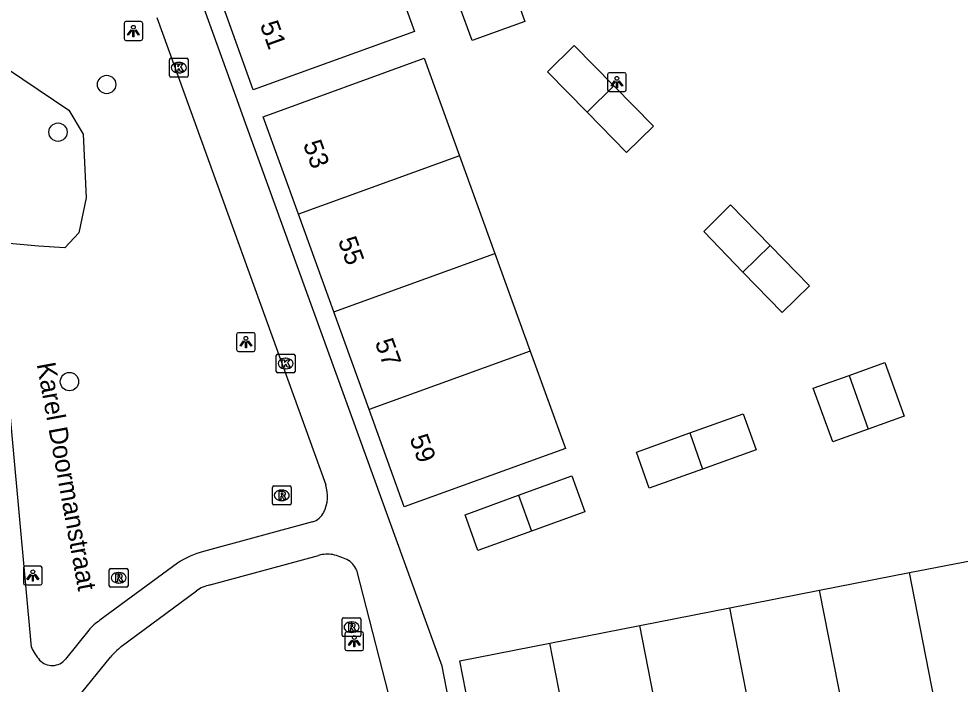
# Model space of a CAD drawing. Extents: x 160379 to 161131, y 383940 to 384849.
# Drawn here: x 160658.5 to 160708.7, y 384516.2 to 384551.6 of the extents above; entities that cross this region are included whole.
import ezdxf

# ---------------------------------------------------------------- set-up
doc = ezdxf.new("R2010")
doc.units = 0
for name, color, linetype in [('IMGEO_Boom', 7, 'Continuous'), ('IMGEO_Groenvoorziening', 7, 'Continuous'), ('IMGEO_Kolk', 7, 'Continuous'), ('IMGEO_Lichtpunt', 7, 'Continuous'), ('IMGEO_Openbare_ruimte_label', 7, 'Continuous'), ('IMGEO_Pand', 7, 'Continuous'), ('IMGEO_Pand_nummerreeks', 7, 'Continuous'), ('IMGEO_Rioolput', 7, 'Continuous'), ('IMGEO_Voetgangersgebied_open', 7, 'Continuous')]:
    doc.layers.add(name, color=color, linetype=linetype)

msp = doc.modelspace()

# ---------------------------------------------------------------- linework, layer by layer
at = {"layer": 'IMGEO_Boom'}
for centre in [(160663.171, 384548.138), (160660.578, 384545.599), (160661.19, 384532.308)]:
    msp.add_circle(centre, 0.489, dxfattribs=at)
at = {"layer": 'IMGEO_Groenvoorziening'}
msp.add_lwpolyline([(160656.229, 384550.075), (160661.151, 384546.774), (160661.917, 384545.486), (160662.071, 384542.104), (160661.684, 384540.236), (160660.94, 384539.438), (160659.532, 384539.533), (160657.181, 384539.738)], dxfattribs=at)
at = {"layer": 'IMGEO_Kolk'}
for p, q in [((160666.521, 384548.609), (160666.521, 384549.461)), ((160666.596, 384549.535), (160667.448, 384549.535)), ((160667.522, 384549.461), (160667.522, 384548.609)), ((160667.009, 384549.315), (160667.034, 384549.315)), ((160667.448, 384548.535), (160666.596, 384548.535)), ((160667.032, 384548.755), (160667.007, 384548.755)), ((160672.217, 384532.844), (160672.217, 384533.696)), ((160672.292, 384533.77), (160673.144, 384533.77)), ((160672.705, 384533.55), (160672.73, 384533.55)), ((160673.218, 384533.696), (160673.218, 384532.844)), ((160672.728, 384532.99), (160672.703, 384532.99)), ((160673.144, 384532.77), (160672.292, 384532.77))]:
    msp.add_line(p, q, dxfattribs=at)
for points in [[(160666.521, 384548.609), (160666.521, 384549.461)], [(160666.596, 384549.535), (160667.448, 384549.535)], [(160667.522, 384549.461), (160667.522, 384548.609)], [(160666.842, 384549.235), (160666.965, 384549.235), (160666.965, 384549.084), (160667.095, 384549.235), (160667.259, 384549.235), (160667.113, 384549.084), (160667.266, 384548.835), (160667.114, 384548.835), (160667.029, 384548.999), (160666.965, 384548.932), (160666.965, 384548.835), (160666.842, 384548.835), (160666.842, 384549.235)], [(160667.448, 384548.535), (160666.596, 384548.535)], [(160672.217, 384532.844), (160672.217, 384533.696)], [(160672.292, 384533.77), (160673.144, 384533.77)], [(160672.538, 384533.47), (160672.661, 384533.47), (160672.661, 384533.319), (160672.791, 384533.47), (160672.955, 384533.47), (160672.809, 384533.319), (160672.962, 384533.07), (160672.81, 384533.07), (160672.725, 384533.234), (160672.661, 384533.167), (160672.661, 384533.07), (160672.538, 384533.07), (160672.538, 384533.47)], [(160673.218, 384533.696), (160673.218, 384532.844)], [(160673.144, 384532.77), (160672.292, 384532.77)]]:
    msp.add_lwpolyline(points, dxfattribs=at)
for centre, start, end in [((160666.598, 384549.459), 91.552, 178.448), ((160666.598, 384549.459), 91.552, 178.448), ((160667.446, 384549.459), 1.552, 88.448), ((160667.446, 384549.459), 1.552, 88.448), ((160666.598, 384548.611), 181.552, 268.448), ((160666.598, 384548.611), 181.552, 268.448), ((160667.446, 384548.611), 271.552, 358.448), ((160667.446, 384548.611), 271.552, 358.448), ((160672.294, 384533.694), 91.552, 178.448), ((160672.294, 384533.694), 91.552, 178.448), ((160673.142, 384533.694), 1.552, 88.448), ((160673.142, 384533.694), 1.552, 88.448), ((160672.294, 384532.846), 181.552, 268.448), ((160672.294, 384532.846), 181.552, 268.448), ((160673.142, 384532.846), 271.552, 358.448), ((160673.142, 384532.846), 271.552, 358.448)]:
    msp.add_arc(centre, 0.0765, start, end, dxfattribs=at)
for centre, major_axis, ratio, start_param, end_param in [((160667.008, 384549.035), (-0.387, 0.002), 0.722429, 4.712389, 7.853982), ((160667.033, 384549.035), (-0.39, 0.002), 0.717154, 1.570796, 4.712389), ((160672.704, 384533.27), (-0.387, 0.002), 0.722429, 4.712389, 7.853982), ((160672.729, 384533.27), (-0.39, 0.002), 0.717154, 1.570796, 4.712389)]:
    msp.add_ellipse(centre, major_axis=major_axis, ratio=ratio, start_param=start_param, end_param=end_param, dxfattribs=at)
at = {"layer": 'IMGEO_Lichtpunt'}
for p, q in [((160665, 384551.487), (160664.192, 384551.487)), ((160665, 384551.487), (160664.192, 384551.487)), ((160664.098, 384551.392), (160664.098, 384550.585)), ((160664.098, 384551.392), (160664.098, 384550.585)), ((160665.094, 384550.585), (160665.094, 384551.392)), ((160665.094, 384550.585), (160665.094, 384551.392)), ((160664.192, 384550.491), (160665, 384550.491)), ((160664.192, 384550.491), (160665, 384550.491)), ((160689.886, 384548.669), (160689.886, 384547.862)), ((160689.886, 384548.669), (160689.886, 384547.862)), ((160690.788, 384548.764), (160689.98, 384548.764)), ((160690.788, 384548.764), (160689.98, 384548.764)), ((160690.882, 384547.862), (160690.882, 384548.669)), ((160690.882, 384547.862), (160690.882, 384548.669)), ((160689.98, 384547.768), (160690.788, 384547.768)), ((160689.98, 384547.768), (160690.788, 384547.768)), ((160671.003, 384534.913), (160670.195, 384534.913)), ((160671.003, 384534.913), (160670.195, 384534.913)), ((160670.101, 384534.818), (160670.101, 384534.011)), ((160670.101, 384534.818), (160670.101, 384534.011)), ((160671.097, 384534.011), (160671.097, 384534.818)), ((160671.097, 384534.011), (160671.097, 384534.818)), ((160670.195, 384533.917), (160671.003, 384533.917)), ((160670.195, 384533.917), (160671.003, 384533.917)), ((160658.736, 384522.38), (160658.736, 384521.573)), ((160658.736, 384522.38), (160658.736, 384521.573)), ((160659.638, 384522.475), (160658.83, 384522.475)), ((160659.638, 384522.475), (160658.83, 384522.475)), ((160659.732, 384521.573), (160659.732, 384522.38)), ((160659.732, 384521.573), (160659.732, 384522.38)), ((160658.83, 384521.479), (160659.638, 384521.479)), ((160658.83, 384521.479), (160659.638, 384521.479)), ((160675.881, 384518.876), (160675.881, 384518.069)), ((160675.881, 384518.876), (160675.881, 384518.069)), ((160676.783, 384518.971), (160675.975, 384518.971)), ((160676.783, 384518.971), (160675.975, 384518.971)), ((160676.877, 384518.069), (160676.877, 384518.876)), ((160676.877, 384518.069), (160676.877, 384518.876)), ((160675.975, 384517.975), (160676.783, 384517.975)), ((160675.975, 384517.975), (160676.783, 384517.975))]:
    msp.add_line(p, q, dxfattribs=at)
for points in [[(160664.472, 384551.056), (160664.511, 384551.028), (160664.323, 384550.766), (160664.285, 384550.793), (160664.472, 384551.056)], [(160664.574, 384551.008), (160664.621, 384551.008), (160664.621, 384550.686), (160664.574, 384550.686), (160664.574, 384551.008)], [(160664.684, 384551.028), (160664.722, 384551.055), (160664.909, 384550.793), (160664.87, 384550.765), (160664.684, 384551.028)], [(160690.26, 384548.333), (160690.299, 384548.305), (160690.111, 384548.043), (160690.073, 384548.07), (160690.26, 384548.333)], [(160690.362, 384548.285), (160690.409, 384548.285), (160690.409, 384547.963), (160690.362, 384547.963), (160690.362, 384548.285)], [(160690.472, 384548.305), (160690.51, 384548.332), (160690.697, 384548.07), (160690.658, 384548.042), (160690.472, 384548.305)], [(160670.475, 384534.482), (160670.514, 384534.454), (160670.326, 384534.192), (160670.288, 384534.219), (160670.475, 384534.482)], [(160670.577, 384534.434), (160670.624, 384534.434), (160670.624, 384534.112), (160670.577, 384534.112), (160670.577, 384534.434)], [(160670.687, 384534.454), (160670.725, 384534.481), (160670.912, 384534.219), (160670.873, 384534.191), (160670.687, 384534.454)], [(160659.11, 384522.044), (160659.149, 384522.016), (160658.961, 384521.754), (160658.923, 384521.781), (160659.11, 384522.044)], [(160659.212, 384521.996), (160659.259, 384521.996), (160659.259, 384521.674), (160659.212, 384521.674), (160659.212, 384521.996)], [(160659.322, 384522.016), (160659.36, 384522.043), (160659.547, 384521.781), (160659.508, 384521.753), (160659.322, 384522.016)], [(160676.255, 384518.54), (160676.294, 384518.512), (160676.106, 384518.25), (160676.068, 384518.277), (160676.255, 384518.54)], [(160676.357, 384518.492), (160676.404, 384518.492), (160676.404, 384518.17), (160676.357, 384518.17), (160676.357, 384518.492)], [(160676.467, 384518.512), (160676.505, 384518.539), (160676.692, 384518.277), (160676.653, 384518.249), (160676.467, 384518.512)]]:
    msp.add_lwpolyline(points, dxfattribs=at)
for centre in [(160664.597, 384551.19), (160690.385, 384548.467), (160670.6, 384534.616), (160659.235, 384522.178), (160676.38, 384518.674)]:
    msp.add_circle(centre, 0.0994, dxfattribs=at)
for centre, start, end in [((160664.192, 384551.392), 90, 180), ((160664.192, 384551.392), 90, 180), ((160665, 384551.392), 0, 90), ((160665, 384551.392), 0, 90), ((160664.192, 384550.585), 180, 270), ((160664.192, 384550.585), 180, 270), ((160665, 384550.585), 270, 0), ((160665, 384550.585), 270, 360), ((160689.98, 384548.669), 90, 180), ((160689.98, 384548.669), 90, 180), ((160690.788, 384548.669), 0, 90), ((160690.788, 384548.669), 0, 90), ((160689.98, 384547.862), 180, 270), ((160689.98, 384547.862), 180, 270), ((160690.788, 384547.862), 270, 0), ((160690.788, 384547.862), 270, 360), ((160670.195, 384534.818), 90, 180), ((160670.195, 384534.818), 90, 180), ((160671.003, 384534.818), 0, 90), ((160671.003, 384534.818), 0, 90), ((160670.195, 384534.011), 180, 270), ((160670.195, 384534.011), 180, 270), ((160671.003, 384534.011), 270, 0), ((160671.003, 384534.011), 270, 360), ((160658.83, 384522.38), 90, 180), ((160658.83, 384522.38), 90, 180), ((160659.638, 384522.38), 0, 90), ((160659.638, 384522.38), 0, 90), ((160658.83, 384521.573), 180, 270), ((160658.83, 384521.573), 180, 270), ((160659.638, 384521.573), 270, 0), ((160659.638, 384521.573), 270, 360), ((160675.975, 384518.876), 90, 180), ((160675.975, 384518.876), 90, 180), ((160676.783, 384518.876), 0, 90), ((160676.783, 384518.876), 0, 90), ((160675.975, 384518.069), 180, 270), ((160675.975, 384518.069), 180, 270), ((160676.783, 384518.069), 270, 0), ((160676.783, 384518.069), 270, 360)]:
    msp.add_arc(centre, 0.0946, start, end, dxfattribs=at)
at = {"layer": 'IMGEO_Pand'}
for points in [[(160677.9, 384555.621), (160679.591, 384550.956), (160670.993, 384547.855), (160669.308, 384552.507)], [(160685.481, 384551.498), (160682.659, 384550.476), (160681.973, 384552.374), (160684.794, 384553.395), (160685.481, 384551.498)], [(160688.789, 384546.663), (160686.675, 384548.816), (160688.102, 384550.217), (160690.216, 384548.064)], [(160673.396, 384541.222), (160671.511, 384546.422), (160680.104, 384549.537), (160681.989, 384544.337)], [(160690.216, 384548.064), (160692.33, 384545.911), (160690.903, 384544.51), (160688.789, 384546.663)], [(160688.789, 384546.663), (160690.216, 384548.064)], [(160681.989, 384544.337), (160673.396, 384541.222)], [(160681.989, 384544.337), (160683.874, 384539.137)], [(160697.105, 384538.147), (160695.015, 384540.299), (160696.434, 384541.723), (160698.558, 384539.558)], [(160675.28, 384536.022), (160673.396, 384541.222)], [(160698.558, 384539.558), (160700.659, 384537.417), (160699.195, 384535.995), (160697.105, 384538.147)], [(160697.105, 384538.147), (160698.558, 384539.558)], [(160675.28, 384536.022), (160683.874, 384539.137)], [(160683.874, 384539.137), (160685.758, 384533.937)], [(160677.165, 384530.822), (160675.28, 384536.022)], [(160685.758, 384533.937), (160687.643, 384528.737), (160679.045, 384525.635), (160677.165, 384530.822)], [(160685.758, 384533.937), (160677.165, 384530.822)], [(160702.767, 384532.64), (160704.679, 384533.323), (160705.699, 384530.47), (160703.788, 384529.782)], [(160703.788, 384529.782), (160701.895, 384529.1), (160700.854, 384531.956), (160702.767, 384532.64)], [(160702.767, 384532.64), (160703.788, 384529.782)], [(160694.269, 384529.57), (160697.117, 384530.589), (160697.802, 384528.674), (160694.956, 384527.649)], [(160694.956, 384527.649), (160692.111, 384526.624), (160691.421, 384528.551), (160694.269, 384529.57)], [(160694.269, 384529.57), (160694.956, 384527.649)], [(160685.13, 384526.254), (160687.977, 384527.293), (160688.674, 384525.363), (160685.821, 384524.336)], [(160685.821, 384524.336), (160682.968, 384523.309), (160682.287, 384525.217), (160685.13, 384526.254)], [(160685.13, 384526.254), (160685.821, 384524.336)], [(160705.987, 384522.128), (160710.782, 384523.068), (160711.912, 384517.267)], [(160701.193, 384521.188), (160705.987, 384522.128)], [(160707.752, 384513.125), (160705.987, 384522.128)], [(160696.398, 384520.249), (160701.193, 384521.188)], [(160702.957, 384512.188), (160701.193, 384521.188)], [(160691.603, 384519.309), (160696.398, 384520.249)], [(160698.162, 384511.251), (160696.398, 384520.249)], [(160686.809, 384518.369), (160691.603, 384519.309)], [(160693.366, 384510.314), (160691.603, 384519.309)], [(160688.571, 384509.377), (160683.77, 384508.439), (160682.014, 384517.429), (160686.809, 384518.369)], [(160688.571, 384509.377), (160686.809, 384518.369)]]:
    msp.add_lwpolyline(points, dxfattribs=at)
at = {"layer": 'IMGEO_Rioolput'}
for p, q in [((160672.01, 384525.82), (160672.01, 384526.672)), ((160672.085, 384526.746), (160672.937, 384526.746)), ((160672.498, 384526.526), (160672.523, 384526.526)), ((160673.011, 384526.672), (160673.011, 384525.82)), ((160672.521, 384525.966), (160672.496, 384525.966)), ((160672.937, 384525.746), (160672.085, 384525.746)), ((160663.386, 384522.356), (160664.238, 384522.356)), ((160663.311, 384521.43), (160663.311, 384522.282)), ((160663.799, 384522.136), (160663.824, 384522.136)), ((160664.312, 384522.282), (160664.312, 384521.43)), ((160664.238, 384521.356), (160663.386, 384521.356)), ((160663.822, 384521.576), (160663.797, 384521.576)), ((160675.732, 384518.797), (160675.732, 384519.649)), ((160675.807, 384519.723), (160676.659, 384519.723)), ((160676.22, 384519.503), (160676.245, 384519.503)), ((160676.733, 384519.649), (160676.733, 384518.797)), ((160676.243, 384518.943), (160676.218, 384518.943)), ((160676.659, 384518.723), (160675.807, 384518.723))]:
    msp.add_line(p, q, dxfattribs=at)
for points in [[(160672.01, 384525.82), (160672.01, 384526.672)], [(160672.085, 384526.746), (160672.937, 384526.746)], [(160672.599, 384526.444), (160672.347, 384526.446), (160672.347, 384526.046)], [(160672.525, 384526.365), (160672.471, 384526.365), (160672.471, 384526.284)], [(160673.011, 384526.672), (160673.011, 384525.82)], [(160672.347, 384526.046), (160672.471, 384526.046), (160672.471, 384526.208), (160672.482, 384526.208)], [(160672.471, 384526.284), (160672.523, 384526.284)], [(160672.529, 384526.179), (160672.6, 384526.046), (160672.74, 384526.046), (160672.675, 384526.172)], [(160672.937, 384525.746), (160672.085, 384525.746)], [(160663.386, 384522.356), (160664.238, 384522.356)], [(160663.311, 384521.43), (160663.311, 384522.282)], [(160663.9, 384522.054), (160663.648, 384522.056), (160663.648, 384521.656)], [(160663.648, 384521.656), (160663.772, 384521.656), (160663.772, 384521.818), (160663.783, 384521.818)], [(160663.826, 384521.975), (160663.772, 384521.975), (160663.772, 384521.894)], [(160663.772, 384521.894), (160663.824, 384521.894)], [(160663.83, 384521.789), (160663.901, 384521.656), (160664.041, 384521.656), (160663.976, 384521.782)], [(160664.312, 384522.282), (160664.312, 384521.43)], [(160664.238, 384521.356), (160663.386, 384521.356)], [(160675.732, 384518.797), (160675.732, 384519.649)], [(160675.807, 384519.723), (160676.659, 384519.723)], [(160676.321, 384519.421), (160676.069, 384519.423), (160676.069, 384519.023)], [(160676.247, 384519.342), (160676.193, 384519.342), (160676.193, 384519.261)], [(160676.733, 384519.649), (160676.733, 384518.797)], [(160676.069, 384519.023), (160676.193, 384519.023), (160676.193, 384519.185), (160676.204, 384519.185)], [(160676.193, 384519.261), (160676.245, 384519.261)], [(160676.251, 384519.156), (160676.322, 384519.023), (160676.462, 384519.023), (160676.397, 384519.149)], [(160676.659, 384518.723), (160675.807, 384518.723)]]:
    msp.add_lwpolyline(points, dxfattribs=at)
for centre, radius, start, end in [((160672.087, 384526.67), 0.0765, 91.552, 178.448), ((160672.087, 384526.67), 0.0765, 91.552, 178.448), ((160672.531, 384526.269), 0.0964, 77.0061, 93.1865), ((160672.545, 384526.326), 0.0378, 276.6634, 79.6772), ((160672.598, 384526.334), 0.109, 350.3612, 89.416), ((160672.596, 384526.334), 0.112, 277.5842, 350.9817), ((160672.935, 384526.67), 0.0765, 1.552, 88.448), ((160672.935, 384526.67), 0.0765, 1.552, 88.448), ((160672.087, 384525.822), 0.0765, 181.552, 268.448), ((160672.087, 384525.822), 0.0765, 181.552, 268.448), ((160672.481, 384526.155), 0.0533, 26.0293, 88.6989), ((160672.507, 384526.473), 0.19, 274.7715, 282.9687), ((160672.58, 384526.119), 0.108, 29.5134, 73.7905), ((160672.935, 384525.822), 0.0765, 271.552, 358.448), ((160672.935, 384525.822), 0.0765, 271.552, 358.448), ((160663.388, 384522.28), 0.0765, 91.552, 178.448), ((160663.388, 384522.28), 0.0765, 91.552, 178.448), ((160664.236, 384522.28), 0.0765, 1.552, 88.448), ((160664.236, 384522.28), 0.0765, 1.552, 88.448), ((160663.782, 384521.765), 0.0533, 26.0293, 88.6989), ((160663.808, 384522.083), 0.19, 274.7715, 282.9687), ((160663.832, 384521.879), 0.0964, 77.0061, 93.1865), ((160663.846, 384521.936), 0.0378, 276.6634, 79.6772), ((160663.899, 384521.944), 0.109, 350.3612, 89.416), ((160663.897, 384521.944), 0.112, 277.5842, 350.9817), ((160663.881, 384521.729), 0.108, 29.5134, 73.7905), ((160663.388, 384521.432), 0.0765, 181.552, 268.448), ((160663.388, 384521.432), 0.0765, 181.552, 268.448), ((160664.236, 384521.432), 0.0765, 271.552, 358.448), ((160664.236, 384521.432), 0.0765, 271.552, 358.448), ((160675.809, 384519.647), 0.0765, 91.552, 178.448), ((160675.809, 384519.647), 0.0765, 91.552, 178.448), ((160676.253, 384519.246), 0.0964, 77.0061, 93.1865), ((160676.267, 384519.303), 0.0378, 276.6634, 79.6772), ((160676.32, 384519.311), 0.109, 350.3612, 89.416), ((160676.318, 384519.311), 0.112, 277.5842, 350.9817), ((160676.657, 384519.647), 0.0765, 1.552, 88.448), ((160676.657, 384519.647), 0.0765, 1.552, 88.448), ((160675.809, 384518.799), 0.0765, 181.552, 268.448), ((160675.809, 384518.799), 0.0765, 181.552, 268.448), ((160676.203, 384519.132), 0.0533, 26.0293, 88.6989), ((160676.229, 384519.45), 0.19, 274.7715, 282.9687), ((160676.302, 384519.096), 0.108, 29.5134, 73.7905), ((160676.657, 384518.799), 0.0765, 271.552, 358.448), ((160676.657, 384518.799), 0.0765, 271.552, 358.448)]:
    msp.add_arc(centre, radius, start, end, dxfattribs=at)
for centre, major_axis, ratio, start_param, end_param in [((160672.497, 384526.246), (-0.387, 0.002), 0.722429, 4.712389, 7.853982), ((160672.522, 384526.246), (-0.39, 0.002), 0.717154, 1.570796, 4.712389), ((160663.798, 384521.856), (-0.387, 0.002), 0.722429, 4.712389, 7.853982), ((160663.823, 384521.856), (-0.39, 0.002), 0.717154, 1.570796, 4.712389), ((160676.219, 384519.223), (-0.387, 0.002), 0.722429, 4.712389, 7.853982), ((160676.244, 384519.223), (-0.39, 0.002), 0.717154, 1.570796, 4.712389)]:
    msp.add_ellipse(centre, major_axis=major_axis, ratio=ratio, start_param=start_param, end_param=end_param, dxfattribs=at)
at = {"layer": 'IMGEO_Voetgangersgebied_open'}
for points in [[(160682.984, 384507.279), (160681.057, 384517.15), (160670.583, 384546.086), (160670.064, 384547.52), (160665.29, 384560.709), (160662.829, 384567.417), (160652.625, 384581.692), (160648.865, 384586.974), (160652.047, 384589.687), (160670.645, 384605.594)], [(160665.84, 384551.711), (160674.853, 384526.804)], [(160659.169, 384518.154), (160657.181, 384539.738)], [(160674.153, 384524.83), (160668.343, 384523.255)], [(160668.689, 384521.472), (160674.478, 384523.05)], [(160666.946, 384522.637), (160662.813, 384519.592)], [(160676.497, 384522.259), (160678.548, 384514.302)], [(160663.95, 384518.188), (160667.964, 384521.156)], [(160662.213, 384519.062), (160660.976, 384517.524)], [(160659.865, 384513.29), (160663.371, 384517.623)]]:
    msp.add_lwpolyline(points, dxfattribs=at)
for centre, radius, start, end in [((160673.034, 384526.198), 1.917, 333.5, 18.4402), ((160673.817, 384525.826), 1.051, 288.639, 332.5952), ((160669.635, 384518.445), 4.98, 105.0415, 122.6855), ((160674.956, 384521.151), 1.958, 81.9393, 104.1422), ((160674.217, 384518.988), 4.225, 65.2077, 76.1179), ((160675.524, 384521.895), 1.038, 20.5003, 63.4181), ((160669.043, 384519.671), 1.836, 101.1093, 125.9918), ((160664.487, 384517.092), 3.008, 123.809, 139.1015), ((160661.151, 384518.929), 2.128, 201.3601, 223.1341), ((160667.261, 384514.216), 5.171, 129.8121, 138.7857), ((160660.266, 384518.086), 0.906, 222.4978, 321.6583)]:
    msp.add_arc(centre, radius, start, end, dxfattribs=at)

# ---------------------------------------------------------------- texts
at = {"layer": 'IMGEO_Openbare_ruimte_label'}
msp.add_text('Karel Doormanstraat', height=1, rotation=280.3766, dxfattribs=at).set_placement((160659.439, 384533.241))
at = {"layer": 'IMGEO_Pand_nummerreeks'}
for s, rotation, p in [('51', 289.9101, (160671.331, 384551.326)), ('53', 289.9215, (160673.633, 384544.971)), ('55', 289.9215, (160675.497, 384539.826)), ('57', 289.9215, (160677.464, 384534.4)), ('59', 289.9215, (160679.314, 384529.295))]:
    msp.add_text(s, height=1, rotation=rotation, dxfattribs=at).set_placement(p)

doc.saveas('drawing.dxf')
